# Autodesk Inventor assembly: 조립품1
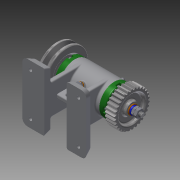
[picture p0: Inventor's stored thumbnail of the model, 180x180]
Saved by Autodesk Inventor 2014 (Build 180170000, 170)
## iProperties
Created: 2016-07
Part Number: 조립품1
Document SubType Name: Assembly
Designer: net
Author: net
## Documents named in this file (16)
- C:\Users\net\Desktop\460707V1002\답안조립품.iam
- C:\Users\net\Desktop\460707V1002\부품1.ipt
- C:\Users\net\Desktop\460707V1002\축.ipt
- C:\Users\net\Desktop\460707V1002\베어링 15 x 32 x 9.ipt
- C:\Users\net\Desktop\460707V1002\키 3 x 3 x 12.ipt
- C:\Users\net\Desktop\460707V1002\커버.ipt
- C:\Users\net\Desktop\460707V1002\니플 M 6 x 0.75.ipt
- C:\Users\net\Desktop\460707V1002\볼트 M 6 x 8.ipt
- C:\Users\net\Desktop\460707V1002\볼트 M4 x 12.ipt
- C:\Users\net\Desktop\460707V1002\오일 실 15 25 7.ipt
- C:\Users\net\Desktop\460707V1002\V벨트풀리.ipt
- C:\Users\net\Desktop\460707V1002\스퍼기어.ipt
- C:\Users\net\Desktop\460707V1002\와셔 6x11.5.ipt
- C:\Users\net\Desktop\460707V1002\스프링와셔 8.ipt
- C:\Users\net\Desktop\460707V1002\너트 M 8.ipt
- C:\Users\net\Desktop\460707V1002\와셔 8x17.ipt
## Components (11 placed, 3 different names)
1. KS B 2023 6002 - 15 x 32 x 9:1
2. KS B 2023 6002 - 15 x 32 x 9:2
3. V벨트풀리:1
4. ISO 4762 M4 x 12:2
5. ISO 4762 M4 x 12:3
6. ISO 4762 M4 x 12:4
7. ISO 4762 M4 x 12:5
8. ISO 4762 M4 x 12:1
9. ISO 4762 M4 x 12:6
10. ISO 4762 M4 x 12:7
11. ISO 4762 M4 x 12:8
